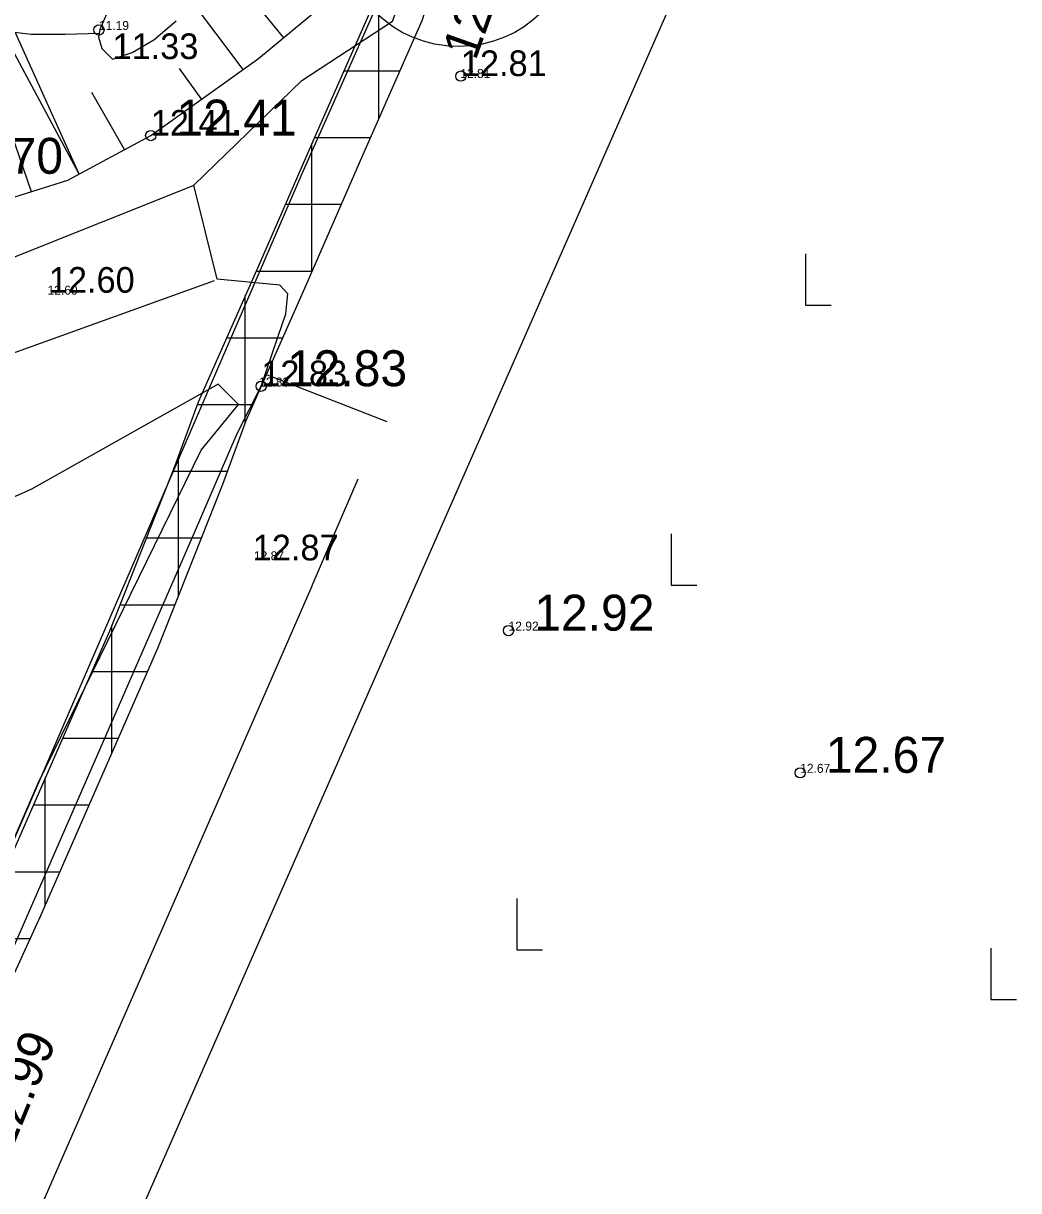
# Model space of a CAD drawing. Extents: x 433497 to 434382, y 6534486 to 6534993.
# Drawn here: x 434137.69 to 434176.46, y 6534741.61 to 6534787.09 of the extents above; entities that cross this region are included whole.
import ezdxf

# ---------------------------------------------------------------- set-up
doc = ezdxf.new("R2010")
doc.units = 0
for name, color, linetype in [('HALJASTUS', 7, 'Continuous'), ('Kaitsevöönd', 7, 'Continuous'), ('kataster', 7, 'Continuous'), ('KORGUS-EH2000', 7, 'Continuous'), ('MOOTKORG-EH2000', 7, 'Continuous'), ('PIIR', 7, 'Continuous'), ('RELJEEF', 7, 'Continuous'), ('TEE', 7, 'Continuous')]:
    doc.layers.add(name, color=color, linetype=linetype)

msp = doc.modelspace()

# ---------------------------------------------------------------- linework, layer by layer
at = {"layer": 'HALJASTUS'}
for p, q in [((434168.155, 6534778.111), (434168.155, 6534776.111)), ((434168.155, 6534776.111), (434169.155, 6534776.111)), ((434162.926, 6534767.203), (434162.926, 6534765.203)), ((434162.926, 6534765.203), (434163.926, 6534765.203)), ((434156.911, 6534752.991), (434156.911, 6534750.991)), ((434175.381, 6534751.057), (434175.381, 6534749.057)), ((434156.911, 6534750.991), (434157.911, 6534750.991)), ((434175.381, 6534749.057), (434176.381, 6534749.057))]:
    msp.add_line(p, q, dxfattribs=at)
msp.add_lwpolyline([(434120.167, 6534715.22), (434123.286, 6534722.97), (434138.264, 6534757.493), (434144.614, 6534770.457), (434146.069, 6534772.243), (434145.275, 6534773.036), (434138, 6534768.935), (434126.491, 6534763.776), (434119.612, 6534756.789), (434114.784, 6534749.844), (434107.728, 6534738.859), (434104.135, 6534730.068), (434101.605, 6534722.143)], dxfattribs=at)
at = {"layer": 'Kaitsevöönd'}
for p, q in [((434151.531, 6534783.359), (434151.531, 6534788.471)), ((434150.175, 6534785.239), (434152.356, 6534785.239)), ((434148.931, 6534777.427), (434148.931, 6534782.41)), ((434149.031, 6534782.639), (434151.215, 6534782.639)), ((434147.892, 6534780.039), (434150.075, 6534780.039)), ((434146.752, 6534777.439), (434148.936, 6534777.439)), ((434146.331, 6534771.509), (434146.331, 6534776.482)), ((434145.607, 6534774.839), (434147.792, 6534774.839)), ((434144.468, 6534772.239), (434146.645, 6534772.239)), ((434143.731, 6534764.776), (434143.731, 6534770.24)), ((434143.504, 6534769.639), (434145.641, 6534769.639)), ((434142.475, 6534767.039), (434144.626, 6534767.039)), ((434141.446, 6534764.439), (434143.597, 6534764.439)), ((434141.131, 6534758.644), (434141.131, 6534763.641)), ((434140.347, 6534761.839), (434142.53, 6534761.839)), ((434139.208, 6534759.239), (434141.391, 6534759.239)), ((434138.531, 6534752.707), (434138.531, 6534757.692)), ((434138.07, 6534756.639), (434140.253, 6534756.639)), ((434136.931, 6534754.039), (434139.114, 6534754.039)), ((434135.756, 6534751.439), (434137.957, 6534751.439))]:
    msp.add_line(p, q, dxfattribs=at)
for points in [[(434128.222, 6534730.093), (434132.174, 6534738.642), (434136.032, 6534747.247), (434138.365, 6534752.329), (434142.93, 6534762.753), (434145.458, 6534769.142), (434146.369, 6534771.613), (434148.646, 6534776.777), (434150.916, 6534781.958), (434153.219, 6534787.206), (434154.721, 6534791.754), (434156.628, 6534795.899), (434159.877, 6534804.556), (434163.808, 6534814.841), (434168.182, 6534825.411), (434171.941, 6534834.072), (434175.51, 6534841.483), (434180.59, 6534850.694), (434185.974, 6534861.252), (434188.694, 6534866.232), (434193.777, 6534875.182), (434200.729, 6534887.95), (434203.323, 6534892.681)], [(434198.974, 6534888.909), (434192.024, 6534876.146), (434186.943, 6534867.198), (434184.199, 6534862.173), (434178.816, 6534851.617), (434173.72, 6534842.375), (434170.114, 6534834.886), (434166.338, 6534826.183), (434161.945, 6534815.568), (434158.005, 6534805.262), (434154.768, 6534796.635), (434152.881, 6534792.54), (434152.839, 6534792.435), (434151.335, 6534787.878), (434149.085, 6534782.762), (434146.815, 6534777.582), (434144.503, 6534772.334), (434143.585, 6534769.845), (434141.077, 6534763.506), (434136.537, 6534753.14), (434134.209, 6534748.069), (434130.352, 6534739.465)]]:
    msp.add_lwpolyline(points, dxfattribs=at)
at = {"layer": 'kataster'}
for points in [[(434117.185, 6534708.296), (434124.427, 6534725.502), (434148.55, 6534781.242), (434178.983, 6534849.691), (434202.394, 6534892.23)], [(434218.021, 6534802.565), (434170.808, 6534805.847), (434126.926, 6534705.929)]]:
    msp.add_lwpolyline(points, dxfattribs=at)
at = {"layer": 'KORGUS-EH2000'}
for centre in [(434140.63, 6534786.83), (434154.731, 6534785.034), (434142.65, 6534782.717), (434142.65, 6534782.717), (434146.953, 6534772.952), (434156.59, 6534763.43), (434167.95, 6534757.89)]:
    msp.add_circle(centre, 0.2, dxfattribs=at)
at = {"layer": 'PIIR'}
msp.add_circle((434154.637, 6534790.783), 4.6, dxfattribs=at)
at = {"layer": 'RELJEEF'}
for p, q in [((434146.249, 6534785.287), (434144.153, 6534788.08)), ((434146.461, 6534788.199), (434147.819, 6534786.524)), ((434139.86, 6534781.218), (434136.58, 6534787.318)), ((434139.86, 6534781.218), (434137.387, 6534786.725)), ((434143.756, 6534785.336), (434144.621, 6534784.125)), ((434140.338, 6534784.407), (434141.621, 6534782.164)), ((434137.062, 6534783.265), (434137.988, 6534780.533))]:
    msp.add_line(p, q, dxfattribs=at)
for points in [[(434116.003, 6534779.573), (434118.33, 6534779.008), (434124.552, 6534778.351), (434128.388, 6534778.248), (434131.064, 6534778.414), (434134.99, 6534779.596), (434139.415, 6534780.978), (434142.65, 6534782.717), (434146.846, 6534785.714), (434149.957, 6534788.306), (434152.414, 6534790.827), (434154.555, 6534795.185), (434159.2, 6534807.543), (434167.641, 6534827.734), (434175.75, 6534844.947), (434185.846, 6534863.98), (434196.935, 6534884.171), (434200.713, 6534891.388)], [(434116.003, 6534779.573), (434118.33, 6534779.008), (434124.552, 6534778.351), (434128.388, 6534778.248), (434131.064, 6534778.414), (434134.99, 6534779.596), (434139.415, 6534780.978), (434142.65, 6534782.717), (434146.846, 6534785.714), (434149.957, 6534788.306), (434152.414, 6534790.827), (434154.555, 6534795.185), (434159.2, 6534807.543), (434167.641, 6534827.734), (434175.75, 6534844.947), (434185.846, 6534863.98), (434196.935, 6534884.171)], [(434140.931, 6534787.45), (434140.664, 6534786.855), (434140.617, 6534786.546), (434140.748, 6534786.113), (434141.16, 6534785.696), (434141.927, 6534785.956)], [(434141.927, 6534785.956), (434142.766, 6534786.441), (434143.643, 6534787.186)], [(434140.664, 6534786.689), (434139.309, 6534786.65), (434137.986, 6534786.65), (434136.36, 6534786.855)]]:
    msp.add_lwpolyline(points, dxfattribs=at)
at = {"layer": 'TEE'}
msp.add_line((434145.237, 6534777.122), (434144.327, 6534780.781), dxfattribs=at)
for points in [[(434144.327, 6534780.781), (434148.542, 6534784.856), (434152.063, 6534787.177), (434164.597, 6534819.637), (434164.618, 6534819.688), (434164.64, 6534819.741), (434164.664, 6534819.795), (434169.822, 6534831.305), (434169.85, 6534831.366), (434169.88, 6534831.428), (434169.913, 6534831.492), (434175.016, 6534841.167), (434175.017, 6534841.169), (434175.019, 6534841.173), (434188.094, 6534865.834), (434188.111, 6534865.865), (434188.13, 6534865.899), (434188.15, 6534865.935), (434194.097, 6534876.248), (434200.82, 6534889.301), (434200.841, 6534889.341), (434200.864, 6534889.384), (434200.889, 6534889.428), (434202.717, 6534892.621)], [(434079.751, 6534762.916), (434087.895, 6534766.788), (434097.926, 6534770.058), (434097.976, 6534770.078), (434098.026, 6534770.088), (434098.086, 6534770.108), (434109.24, 6534772.987), (434122.531, 6534774.391), (434133.956, 6534776.648), (434144.207, 6534780.731), (434144.327, 6534780.781)], [(434145.12, 6534777.059), (434135.48, 6534773.589), (434121.427, 6534771.071), (434109.25, 6534769.165), (434099.32, 6534766.909), (434088.868, 6534763.558), (434081.095, 6534760.008)], [(434146.018, 6534771.113), (434146.953, 6534772.952), (434147.615, 6534774.896), (434147.913, 6534775.772), (434147.995, 6534776.549), (434147.684, 6534776.895), (434145.237, 6534777.122)], [(434147.185, 6534773.396), (434151.848, 6534771.58)], [(434119.091, 6534708.897), (434123.118, 6534718.63), (434123.124, 6534718.644), (434123.131, 6534718.659), (434123.138, 6534718.676), (434134.061, 6534743.666), (434144.319, 6534767.161), (434146.018, 6534771.113)], [(434150.712, 6534769.33), (434148.927, 6534765.179), (434148.926, 6534765.176), (434148.924, 6534765.172), (434148.922, 6534765.166), (434138.66, 6534741.665), (434138.66, 6534741.664), (434127.747, 6534716.695), (434124.038, 6534707.733)]]:
    msp.add_lwpolyline(points, dxfattribs=at)

# ---------------------------------------------------------------- texts
at = {"layer": 'KORGUS-EH2000'}
for s, rotation, p in [('12.81', 70.508, (434155.305, 6534785.607)), ('12.99', 67.627, (434137.212, 6534743.115))]:
    msp.add_text(s, height=1.4, rotation=rotation, dxfattribs=at).set_placement(p)
for s, p in [('12.41', (434143.65, 6534782.717)), ('11.70', (434134.547, 6534781.228)), ('12.83', (434147.953, 6534772.952)), ('12.92', (434157.59, 6534763.43)), ('12.67', (434168.95, 6534757.89))]:
    msp.add_text(s, height=1.4, dxfattribs=at).set_placement(p)
at = {"layer": 'MOOTKORG-EH2000'}
for s, height, p in [('11.19', 0.35, (434140.63, 6534786.83)), ('11.33', 1, (434141.16, 6534785.696)), ('12.81', 1, (434154.731, 6534785.034)), ('12.81', 0.35, (434154.71, 6534784.96)), ('12.41', 1, (434142.65, 6534782.717)), ('12.60', 1, (434138.678, 6534776.594)), ('12.60', 0.35, (434138.63, 6534776.52)), ('12.83', 1, (434146.953, 6534772.952)), ('12.83', 0.35, (434146.87, 6534772.94)), ('12.87', 1, (434146.622, 6534766.167)), ('12.87', 0.35, (434146.67, 6534766.17)), ('12.92', 0.35, (434156.59, 6534763.43)), ('12.67', 0.35, (434167.95, 6534757.89))]:
    msp.add_text(s, height=height, dxfattribs=at).set_placement(p)

doc.saveas('drawing.dxf')
